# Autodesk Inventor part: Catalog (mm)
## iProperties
Shininess: 64.0
Length Units: 11269
Angle Units: 11279
Time Units: 11290
Mass Units: 11283
Length Display Precision: 3
Angle Display Precision: 2
Compacted: True
Part Number: Catalog (mm)
Document SubType Name: Modeling
Created: 2002-07
Density: 1 g/cm^3
Density: 0.0
Volumn: 0.0
Area: 0.0
PropertySet Name: Model Information
Control State: 0
Master: False
Checked Out: False
